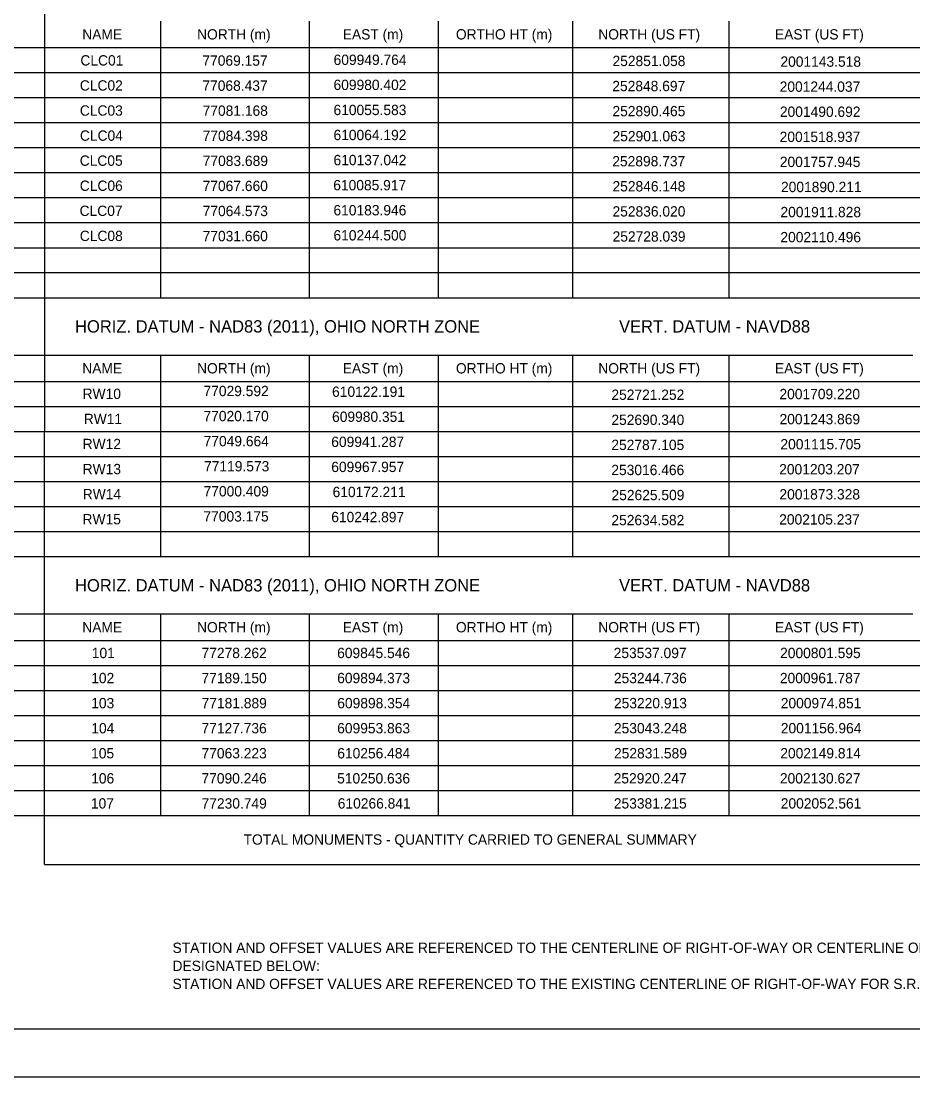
# Model space of a CAD drawing. Extents: x -4451 to 6119, y -1533 to 848.
# Drawn here: x 392.9 to 579.5, y 0 to 221 of the extents above; entities that cross this region are included whole.
import ezdxf

# ---------------------------------------------------------------- set-up
doc = ezdxf.new("R2010")
doc.units = 0
for name, color, linetype in [('SC_Scratch1', 7, 'Continuous'), ('SH_Cut_Line', 7, 'Continuous'), ('SH_Data', 7, 'Continuous')]:
    doc.layers.add(name, color=color, linetype=linetype)

msp = doc.modelspace()

# ---------------------------------------------------------------- linework, layer by layer
at = {"layer": 'SC_Scratch1'}
for p, q in [((397.78, 44.46), (397.85, 421.7)), ((422.12, 163.15), (422.12, 221.01)), ((453.21, 163.15), (453.21, 221.01)), ((480.25, 163.24), (480.25, 221.01)), ((508.37, 163.24), (508.37, 221.01)), ((541.09, 163.15), (541.09, 221.01)), ((30.05, 215.46), (640.05, 215.46)), ((30.05, 210.23), (640.05, 210.23)), ((30.05, 204.99), (640.05, 204.99)), ((30.05, 199.76), (640.05, 199.76)), ((30.05, 194.52), (640.05, 194.52)), ((30.05, 189.29), (640.05, 189.29)), ((30.05, 184.05), (640.05, 184.05)), ((30.05, 178.82), (640.05, 178.82)), ((30.05, 173.58), (640.05, 173.58)), ((30.05, 168.35), (640.05, 168.35)), ((30.05, 163.11), (640.05, 163.11)), ((30.05, 163.11), (640.05, 163.11)), ((30.05, 163.11), (640.05, 163.11)), ((30.05, 163.11), (640.05, 163.11)), ((30.05, 163.11), (640.05, 163.11)), ((30.05, 163.11), (640.05, 163.11)), ((30.05, 163.11), (640.05, 163.11)), ((30.05, 151.1), (579.48, 151.1)), ((422.12, 108.87), (422.12, 151.1)), ((453.21, 108.9), (453.21, 151.1)), ((480.25, 108.91), (480.25, 151.1)), ((508.37, 108.89), (508.37, 151.1)), ((541.09, 108.89), (541.09, 151.1)), ((30.05, 145.56), (640.05, 145.56)), ((30.05, 140.32), (640.05, 140.32)), ((30.05, 135.09), (640.05, 135.09)), ((30.05, 129.85), (640.05, 129.85)), ((30.05, 124.62), (640.05, 124.62)), ((30.05, 119.38), (640.05, 119.38)), ((30.05, 114.15), (640.05, 114.15)), ((30.05, 108.91), (640.05, 108.91)), ((30.05, 108.91), (640.05, 108.91)), ((30.05, 108.91), (640.05, 108.91)), ((30.05, 96.9), (579.48, 96.9)), ((422.12, 54.67), (422.12, 96.9)), ((453.21, 54.7), (453.21, 96.9)), ((480.25, 54.71), (480.25, 96.9)), ((508.37, 54.69), (508.37, 96.9)), ((541.09, 54.69), (541.09, 96.9)), ((30.05, 91.36), (640.05, 91.36)), ((30.05, 86.13), (640.05, 86.13)), ((30.05, 80.89), (640.05, 80.89)), ((30.05, 75.65), (640.05, 75.65)), ((30.05, 70.42), (640.05, 70.42)), ((30.05, 65.18), (640.05, 65.18)), ((30.05, 59.95), (640.05, 59.95)), ((30.05, 54.71), (640.05, 54.71)), ((30.05, 54.71), (640.05, 54.71)), ((397.78, 44.46), (640.05, 44.46))]:
    msp.add_line(p, q, dxfattribs=at)
at = {"layer": 'SH_Cut_Line'}
msp.add_lwpolyline([(0, 0), (680, 0), (680, 440), (0, 440)], close=True, dxfattribs=at)
at = {"layer": 'SH_Data'}
msp.add_lwpolyline([(30, 430), (670, 430), (670, 10), (30, 10)], close=True, dxfattribs=at)

# ---------------------------------------------------------------- texts
at = {"layer": 'SC_Scratch1'}
for s, height, p in [('NAME', 2.157, (405.68, 217.16)), ('NORTH (m)', 2.157, (429.71, 217.16)), ('EAST (m)', 2.157, (460.2, 217.16)), ('ORTHO HT (m)', 2.1565, (483.88, 217.16)), ('NORTH (US FT)', 2.1565, (513.68, 217.16)), ('EAST (US FT)', 2.1565, (550.66, 217.16)), ('CLC01', 2.16, (405.29, 211.71)), ('77069.157', 2.16, (430.82, 211.67)), ('609949.764', 2.16, (458.28, 211.83)), ('252851.058', 2.16, (516.65, 211.59)), ('2001143.518', 2.16, (551.8, 211.45)), ('CLC02', 2.16, (405.17, 206.46)), ('77068.437', 2.16, (430.82, 206.42)), ('609980.402', 2.16, (458.26, 206.58)), ('252848.697', 2.16, (516.61, 206.34)), ('2001244.037', 2.16, (551.64, 206.21)), ('CLC03', 2.16, (405.17, 201.21)), ('77081.168', 2.16, (430.87, 201.18)), ('610055.583', 2.16, (458.26, 201.33)), ('252890.465', 2.16, (516.64, 201.09)), ('2001490.692', 2.16, (551.69, 200.96)), ('CLC04', 2.16, (405.19, 195.96)), ('77084.398', 2.16, (430.87, 195.93)), ('610064.192', 2.16, (458.26, 196.09)), ('252901.063', 2.16, (516.66, 195.84)), ('2001518.937', 2.16, (551.64, 195.71)), ('CLC05', 2.16, (405.15, 190.72)), ('77083.689', 2.16, (430.89, 190.68)), ('610137.042', 2.16, (458.26, 190.84)), ('252898.737', 2.16, (516.61, 190.6)), ('2001757.945', 2.16, (551.67, 190.46)), ('CLC06', 2.16, (405.16, 185.47)), ('77067.660', 2.16, (430.87, 185.43)), ('610085.917', 2.16, (458.21, 185.59)), ('252846.148', 2.16, (516.65, 185.35)), ('2001890.211', 2.16, (551.92, 185.21)), ('CLC07', 2.16, (405.12, 180.22)), ('77064.573', 2.16, (430.88, 180.18)), ('610183.946', 2.16, (458.25, 180.34)), ('252836.020', 2.16, (516.65, 180.1)), ('2001911.828', 2.16, (551.8, 179.96)), ('CLC08', 2.16, (405.16, 174.97)), ('77031.660', 2.16, (430.87, 174.93)), ('610244.500', 2.16, (458.25, 175.09)), ('252728.039', 2.16, (516.67, 174.85)), ('2002110.496', 2.16, (551.79, 174.71)), ('HORIZ. DATUM - NAD83 (2011), OHIO NORTH ZONE', 2.5878, (404.16, 155.81)), ('VERT. DATUM - NAVD88', 2.5878, (518.02, 155.81)), ('NAME', 2.157, (405.68, 147.25)), ('NORTH (m)', 2.157, (429.71, 147.25)), ('EAST (m)', 2.157, (460.2, 147.25)), ('ORTHO HT (m)', 2.1565, (483.88, 147.25)), ('NORTH (US FT)', 2.1565, (513.68, 147.25)), ('EAST (US FT)', 2.1565, (550.66, 147.25)), ('RW10', 2.16, (405.75, 141.91)), ('77029.592', 2.16, (431.05, 142.5)), ('610122.191', 2.16, (457.96, 142.35)), ('252721.252', 2.16, (516.42, 141.72)), ('2001709.220', 2.16, (551.59, 141.86)), ('77020.170', 2.16, (431.05, 137.25)), ('609980.351', 2.16, (457.96, 137.11)), ('RW11', 2.16, (405.99, 136.66)), ('252690.340', 2.16, (516.42, 136.47)), ('2001243.869', 2.16, (551.61, 136.61)), ('RW12', 2.16, (405.76, 131.41)), ('77049.664', 2.16, (431.08, 132)), ('609941.287', 2.16, (457.79, 131.86)), ('252787.105', 2.16, (516.41, 131.22)), ('2001115.705', 2.16, (551.8, 131.36)), ('RW13', 2.16, (405.76, 126.16)), ('77119.573', 2.16, (431.17, 126.75)), ('609967.957', 2.16, (457.79, 126.61)), ('2001203.207', 2.16, (551.54, 126.12)), ('253016.466', 2.16, (516.41, 125.97)), ('RW14', 2.16, (405.78, 120.91)), ('77000.409', 2.16, (431.07, 121.51)), ('610172.211', 2.16, (458.07, 121.36)), ('252625.509', 2.16, (516.44, 120.72)), ('2001873.328', 2.16, (551.59, 120.87)), ('RW15', 2.16, (405.74, 115.66)), ('77003.175', 2.16, (431.04, 116.26)), ('610242.897', 2.16, (457.79, 116.11)), ('252634.582', 2.16, (516.42, 115.48)), ('2002105.237', 2.16, (551.54, 115.62)), ('HORIZ. DATUM - NAD83 (2011), OHIO NORTH ZONE', 2.5878, (404.16, 101.61)), ('VERT. DATUM - NAVD88', 2.5878, (518.02, 101.61)), ('NAME', 2.157, (405.68, 93.05)), ('NORTH (m)', 2.157, (429.71, 93.05)), ('EAST (m)', 2.157, (460.2, 93.05)), ('ORTHO HT (m)', 2.1565, (483.88, 93.05)), ('NORTH (US FT)', 2.1565, (513.68, 93.05)), ('EAST (US FT)', 2.1565, (550.66, 93.05)), ('101', 2.16, (407.67, 87.66)), ('77278.262', 2.16, (430.64, 87.66)), ('609845.546', 2.16, (459.02, 87.66)), ('253537.097', 2.16, (516.9, 87.66)), ('2000801.595', 2.16, (551.73, 87.66)), ('102', 2.16, (407.55, 82.41)), ('77189.150', 2.16, (430.63, 82.41)), ('609894.373', 2.16, (459.03, 82.41)), ('253244.736', 2.16, (516.94, 82.41)), ('2000961.787', 2.16, (551.69, 82.41)), ('103', 2.16, (407.55, 77.16)), ('77181.889', 2.16, (430.65, 77.16)), ('609898.354', 2.16, (459.05, 77.16)), ('253220.913', 2.16, (516.96, 77.16)), ('2000974.851', 2.16, (551.87, 77.16)), ('104', 2.16, (407.57, 71.91)), ('77127.736', 2.16, (430.63, 71.91)), ('609953.863', 2.16, (459.03, 71.91)), ('253043.248', 2.16, (516.95, 71.91)), ('2001156.964', 2.16, (551.88, 71.91)), ('105', 2.16, (407.53, 66.67)), ('77063.223', 2.16, (430.64, 66.67)), ('610256.484', 2.16, (459.05, 66.67)), ('252831.589', 2.16, (516.97, 66.67)), ('2002149.814', 2.16, (551.77, 66.67)), ('106', 2.16, (407.54, 61.42)), ('77090.246', 2.16, (430.63, 61.42)), ('510250.636', 2.16, (459.02, 61.42)), ('252920.247', 2.16, (516.9, 61.42)), ('2002130.627', 2.16, (551.69, 61.42)), ('107', 2.16, (407.49, 56.17)), ('77230.749', 2.16, (430.65, 56.17)), ('610266.841', 2.16, (459.15, 56.17)), ('253381.215', 2.16, (516.93, 56.17)), ('2002052.561', 2.16, (551.87, 56.17)), ('TOTAL MONUMENTS - QUANTITY CARRIED TO GENERAL SUMMARY', 2.1565, (439.45, 48.61)), ('STATION AND OFFSET VALUES ARE REFERENCED TO THE CENTERLINE OF RIGHT-OF-WAY OR CENTERLINE OF CONSTRUCTION AS ', 2.16, (424.57, 25.95)), ('DESIGNATED BELOW:', 2.16, (424.57, 22.17)), ('STATION AND OFFSET VALUES ARE REFERENCED TO THE EXISTING CENTERLINE OF RIGHT-OF-WAY FOR S.R. 229', 2.16, (424.57, 18.39))]:
    msp.add_text(s, height=height, dxfattribs=at).set_placement(p)

doc.saveas('drawing.dxf')
